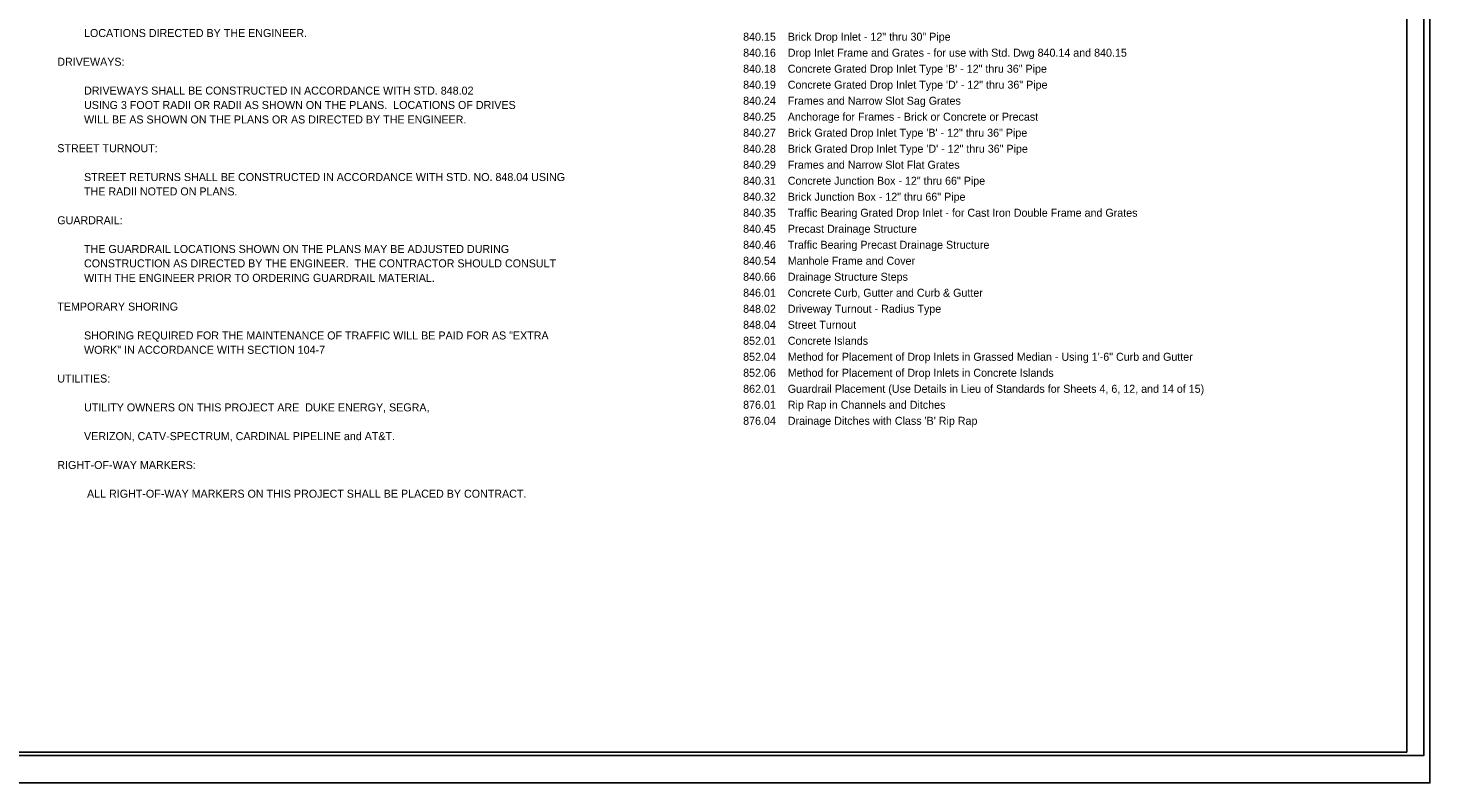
# Model space of a CAD drawing. Extents: x 3312684 to 3314684, y -677777 to -676682.
# Drawn here: x 3313659 to 3314684, y -677777 to -677225 of the extents above; entities that cross this region are included whole.
import ezdxf

# ---------------------------------------------------------------- set-up
doc = ezdxf.new("R2010")
doc.units = 0
for name, color, linetype in [('Default', 7, 'Continuous'), ('Sheet Plan CELL', 7, 'Continuous'), ('Sheet Plot Border Inside CELL', 7, 'Continuous'), ('Sheet Plot Border Outside CELL', 7, 'Continuous')]:
    doc.layers.add(name, color=color, linetype=linetype)

msp = doc.modelspace()

# ---------------------------------------------------------------- linework, layer by layer
at = {"layer": 'Sheet Plan CELL'}
msp.add_lwpolyline([(3314666.7, -676704.5), (3313166.7, -676704.5), (3313166.7, -677754.5), (3314666.7, -677754.5)], close=True, dxfattribs=at)
at = {"layer": 'Sheet Plot Border Inside CELL'}
msp.add_lwpolyline([(3313013.2, -677757), (3314679.2, -677757), (3314679.2, -676702), (3313013.2, -676702)], close=True, dxfattribs=at)
at = {"layer": 'Sheet Plot Border Outside CELL'}
msp.add_lwpolyline([(3313000.2, -677777), (3314683.7, -677777), (3314683.7, -676682), (3313000.2, -676682)], close=True, dxfattribs=at)

# ---------------------------------------------------------------- texts
at = {"layer": 'Default'}
for s, height, p in [('         LOCATIONS DIRECTED BY THE ENGINEER.  ', 5.849, (3313680.4, -677231.7)), ('840.15    Brick Drop Inlet - 12" thru 30" Pipe', 5.85, (3314181.7, -677234.4)), ('DRIVEWAYS:  ', 5.849, (3313680.4, -677252.7)), ('840.16    Drop Inlet Frame and Grates - for use with Std. Dwg 840.14 and 840.15', 5.85, (3314181.7, -677246.1)), ('840.18    Concrete Grated Drop Inlet Type \'B\' - 12" thru 36" Pipe', 5.85, (3314181.7, -677257.8)), ('         DRIVEWAYS SHALL BE CONSTRUCTED IN ACCORDANCE WITH STD. 848.02', 5.849, (3313680.4, -677273.8)), ('840.19    Concrete Grated Drop Inlet Type \'D\' - 12" thru 36" Pipe', 5.85, (3314181.7, -677269.5)), ('         USING 3 FOOT RADII OR RADII AS SHOWN ON THE PLANS.  LOCATIONS OF DRIVES', 5.849, (3313680.4, -677284.3)), ('840.24    Frames and Narrow Slot Sag Grates', 5.85, (3314181.7, -677281.2)), ('         WILL BE AS SHOWN ON THE PLANS OR AS DIRECTED BY THE ENGINEER.  ', 5.849, (3313680.4, -677294.9)), ('840.25    Anchorage for Frames - Brick or Concrete or Precast', 5.85, (3314181.7, -677292.9)), ('840.27    Brick Grated Drop Inlet Type \'B\' - 12" thru 36" Pipe', 5.85, (3314181.7, -677304.6)), ('STREET TURNOUT:  ', 5.849, (3313680.4, -677315.9)), ('840.28    Brick Grated Drop Inlet Type \'D\' - 12" thru 36" Pipe', 5.85, (3314181.7, -677316.3)), ('         STREET RETURNS SHALL BE CONSTRUCTED IN ACCORDANCE WITH STD. NO. 848.04 USING ', 5.849, (3313680.4, -677337)), ('840.29    Frames and Narrow Slot Flat Grates', 5.85, (3314181.7, -677328)), ('         THE RADII NOTED ON PLANS.  ', 5.849, (3313680.4, -677347.5)), ('840.31    Concrete Junction Box - 12" thru 66" Pipe', 5.85, (3314181.7, -677339.7)), ('840.32    Brick Junction Box - 12" thru 66" Pipe', 5.85, (3314181.7, -677351.4)), ('840.35    Traffic Bearing Grated Drop Inlet - for Cast Iron Double Frame and Grates', 5.85, (3314181.7, -677363.1)), ('GUARDRAIL:  ', 5.849, (3313680.4, -677368.6)), ('840.45    Precast Drainage Structure', 5.85, (3314181.7, -677374.8)), ('840.46    Traffic Bearing Precast Drainage Structure', 5.85, (3314181.7, -677386.5)), ('         THE GUARDRAIL LOCATIONS SHOWN ON THE PLANS MAY BE ADJUSTED DURING ', 5.849, (3313680.4, -677389.6)), ('840.54    Manhole Frame and Cover', 5.85, (3314181.7, -677398.2)), ('         CONSTRUCTION AS DIRECTED BY THE ENGINEER.  THE CONTRACTOR SHOULD CONSULT', 5.849, (3313680.4, -677400.1)), ('         WITH THE ENGINEER PRIOR TO ORDERING GUARDRAIL MATERIAL.', 5.849, (3313680.4, -677410.7)), ('840.66    Drainage Structure Steps', 5.85, (3314181.7, -677409.9)), ('846.01    Concrete Curb, Gutter and Curb & Gutter', 5.85, (3314181.7, -677421.6)), ('TEMPORARY SHORING', 5.849, (3313680.4, -677431.7)), ('848.02    Driveway Turnout - Radius Type', 5.85, (3314181.7, -677433.3)), ('848.04    Street Turnout', 5.85, (3314181.7, -677445)), ('         SHORING REQUIRED FOR THE MAINTENANCE OF TRAFFIC WILL BE PAID FOR AS "EXTRA', 5.849, (3313680.4, -677452.8)), ('852.01    Concrete Islands', 5.85, (3314181.7, -677456.7)), ('         WORK" IN ACCORDANCE WITH SECTION 104-7', 5.849, (3313680.4, -677463.3)), ('852.04    Method for Placement of Drop Inlets in Grassed Median - Using 1\'-6" Curb and Gutter', 5.85, (3314181.7, -677468.4)), ('852.06    Method for Placement of Drop Inlets in Concrete Islands', 5.85, (3314181.7, -677480.1)), ('UTILITIES:  ', 5.849, (3313680.4, -677484.3)), ('862.01    Guardrail Placement (Use Details in Lieu of Standards for Sheets 4, 6, 12, and 14 of 15)', 5.85, (3314181.7, -677491.8)), ('         UTILITY OWNERS ON THIS PROJECT ARE  DUKE ENERGY, SEGRA,', 5.849, (3313680.4, -677505.4)), ('876.01    Rip Rap in Channels and Ditches', 5.85, (3314181.7, -677503.5)), ("876.04    Drainage Ditches with Class 'B' Rip Rap", 5.85, (3314181.7, -677515.2)), ('         VERIZON, CATV-SPECTRUM, CARDINAL PIPELINE and AT&T.', 5.849, (3313680.4, -677526.4)), ('RIGHT-OF-WAY MARKERS:  ', 5.849, (3313680.4, -677547.5)), ('          ALL RIGHT-OF-WAY MARKERS ON THIS PROJECT SHALL BE PLACED BY CONTRACT. ', 5.849, (3313680.4, -677568.5))]:
    msp.add_text(s, height=height, dxfattribs=at).set_placement(p)

doc.saveas('drawing.dxf')
